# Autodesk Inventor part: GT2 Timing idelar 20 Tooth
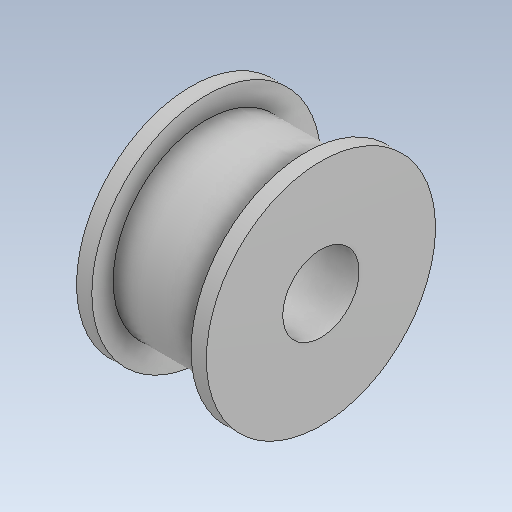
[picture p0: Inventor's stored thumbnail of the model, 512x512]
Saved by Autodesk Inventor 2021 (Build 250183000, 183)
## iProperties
Created: 2026-10
Part Number: GT2 Timing idelar 20 Tooth
Material: Steel
Document SubType Name: Modeling
Designer: hp
Density: 7.85 g/cm^3
Appearance: Default
Author: hp
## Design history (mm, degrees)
feature "Body1"
body "Solid1"
